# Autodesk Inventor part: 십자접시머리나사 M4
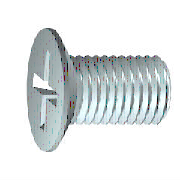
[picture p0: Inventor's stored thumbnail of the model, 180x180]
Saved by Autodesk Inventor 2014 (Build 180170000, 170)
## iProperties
IsCustomPart: 0
Created: 2012-02
Part Number: 십자접시머리나사 M4
Material: 강철, 연강
Description: 십자 오목 머리 나사
Document SubType Name: Modeling
Standard: KS B 1023
Designer: mduedu
Standards Organization: KS
Language: ko-KR
Size Designation: A  M 4 x 12 - H
Categories: <MemberInstance><Categories><Category DisplayName="조임쇠" InternalName="e4da775c-781d-43d5-af7c-5136215cf5a6" Mnemonic="FSTN"><Category DisplayName="볼트" InternalN
Density: 7.86 g/cm^3
Mass: 1.50482 g
Surface Area: 2.78557 cm^2
Volume: 0.191453 cm^3
Appearance: 주황색
Author: mduedu
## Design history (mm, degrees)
body "Solid1"
sketch "스케치1"
  geometry: L1 (2.6, 0)-(12, 0); L2 (12, 0)-(12, 2); L3 (12, 2)-(4.1, 2); L4 (4.1, 2)-(3.671, 1.785); L5 (3.671, 1.785)-(2.7, 1.785); L6 (0, 4.2)-(0, 2.4); L7 (0, 2.4)-(1.801, 1.502); L8 (1.801, 1.502)-(2.6, 0); L9 (-2.4, 0)-(14.4, 0) reference; L10 (0, -0.84)-(0, 5.04) reference; L11 (0, 4.2)-(0.285, 4.2); L12 (0.285, 4.2)-(2.7, 1.785); L13 (4.1, 2)-(2.485, 2)
  constraints: 22 end point, 3 parallel, 3 perpendicular, 2 collinear, 1 horizontal, 1 point on line
  dimensions: "d1" = 7.9 distance of L2.end L3.end (= GEL); "d2" = 4 diameter of L3 L1 (= GD); "d3" = 3.57058 diameter of L5 L1 (= BDM); "d4" = 4.8 diameter of L6.end L1 (= SDM); "d5" = 26.5 deg angle of L7 L1; "d6" = 62 deg angle of L8 L1; "d7" = 2.6 distance from line of L1.start L6 (= INTI); "d8" = 0.42941 horizontal distance of L4.end L3.end (= GAL); "d12" = 8.4 diameter of L11 L1 (= KOD); "d13" = 45 deg angle of L12 L1 (= 0.5 x SEWI); "d15" = 12 distance between parallel lines of L2 L6 (= NLG); "d24" = 2.7 distance from line of L5.end L6 (= KOH)
revolve "본체" stored, may be unused: angle "d16" = 90 deg
sketch "스케치2"
  geometry: L1 (0, 2.4)-(0, 0); L2 (0, 0)-(2.4, 0); L3 (0, 0)-(1.697, 1.697); L4 (0.312, 2.38)-(0.408, 0.734); L5 (2.38, 0.312)-(0.734, 0.408); L6 (0, -5.88)-(0, 5.88) reference; L7 (-5.88, 0)-(5.88, 0) reference; L8 (2.38, -0.312)-(0.734, -0.408); L9 (0.312, -2.38)-(0.408, -0.734); L10 (-0.312, -2.38)-(-0.408, -0.734); L11 (-2.38, -0.312)-(-0.734, -0.408); L12 (-2.38, 0.312)-(-0.734, 0.408); L13 (-0.312, 2.38)-(-0.408, 0.734); A1 r 0.72 centre (0, 0) between (0.72, 0) and (0, 0.72); A2 r 0.84 centre (0, 0) between (0.84, 0) and (0, 0.84); A3 r 2.4 centre (0, 0) between (2.38, 0.312) and (0.312, 2.38); A4 r 2.4 centre (0, 0) between (0.312, 2.38) and (0, 2.4); A5 r 2.4 centre (0, 0) between (2.4, 0) and (2.38, 0.312); A6 r 2.4 centre (0, 0) between (0, -2.4) and (0.312, -2.38); A7 r 2.4 centre (0, 0) between (0.312, -2.38) and (2.38, -0.312); A8 r 2.4 centre (0, 0) between (2.38, -0.312) and (2.4, 0); A9 r 2.4 centre (0, 0) between (0, 2.4) and (-0.312, 2.38); A10 r 2.4 centre (0, 0) between (-0.312, 2.38) and (-2.38, 0.312); A11 r 2.4 centre (0, 0) between (-2.38, 0.312) and (-2.4, 0); A12 r 2.4 centre (0, 0) between (-2.4, 0) and (-2.38, -0.312); A13 r 2.4 centre (0, 0) between (-2.38, -0.312) and (-0.312, -2.38); A14 r 2.4 centre (0, 0) between (-0.312, -2.38) and (0, -2.4); A15 r 0.347 centre (0.755, 0.755) between (0.408, 0.734) and (0.734, 0.408); A16 r 0.347 centre (0.755, -0.755) between (0.734, -0.408) and (0.408, -0.734); A17 r 0.347 centre (-0.755, -0.755) between (-0.408, -0.734) and (-0.734, -0.408); A18 r 0.347 centre (-0.755, 0.755) between (-0.734, 0.408) and (-0.408, 0.734); 3 further points
  constraints: 41 point on circle, 22 end point, 22 symmetric about line, 18 centre point, 11 coincident, 4 point on line, 3 tangent, 2 collinear, 1 perpendicular, 1 vertical, 19 other
  dimensions: "d17" = 1.44 diameter of A1 (= 0.3 x SDM); "d18" = 1.68 diameter of A2 (= 0.35 x SDM); "d19" = 4.8 diameter of A3 (= SDM); "d20" = 45 deg angle of L3 L2; "d21" = 0.3115 distance from line of L4.start L1 (= 0.5 x SBR)
extrude "슬롯" join sketch "스케치2" taper "d22" = 5 deg; stored distance "d79" = 25.4
fillet "모깎기1" dims "d23" = 0.1246 (= 0.2 x SBR)
feature "스레드" dims "d10" = 7.9 (= GEL), "d11" = 0
chamfer "모따기1" distance "d25" = 0.42941 (= -0.5 x SPD + 0.5 x GD); stored, may be unused: second distance "d26" = 0.21471 (= 0.5 x GAL), angle "d88" = 45 deg
workplane "Work Plane2"
other parameters: "NLG" = 12 [user parameter; used in 1 equation term], "GEL" = 7.9 [user parameter; used in 2 equation terms], "GAL" = 0.42941 (= 0.61345 x PTC) [user parameter; used in 3 equation terms], "SPD" = 3.14117 (= NND - 1.2269 x PTC) [user parameter; used in 1 equation term], "KOD" = 8.4 [user parameter; used in 1 equation term], "KOH" = 2.7 [user parameter; used in 1 equation term], "SBR" = 0.623 [user parameter; used in 2 equation terms], "INTI" = 2.6 [user parameter; used in 1 equation term], "SDM" = 4.8 [user parameter; used in 5 equation terms], "GD" = 4 (= NND) [user parameter; used in 2 equation terms], "BDM" = 3.57058 (= NND - GAL) [user parameter; used in 1 equation term], "SEWI" = 90 deg [user parameter; used in 1 equation term], "d9" = 4.8 (= SDM), "d27" = 0, "d91" = 0, "d92" = 0, "GUL" = 0.42941 (= 0.61345 x PTC) [user parameter], "TOA" = 30 deg [user parameter], "EPV" = 4.7 [user parameter], "THREADDIA" = 4 [user parameter; used in 1 equation term], "TPU" = 14.28571 (computed from PTC) [user parameter], "PTC" = 0.7 [user parameter; used in 5 equation terms], "NND" = 4 [user parameter; used in 3 equation terms], "GD1" = 3.14117 (= THREADDIA - 1.2269 x PTC) [user parameter]
